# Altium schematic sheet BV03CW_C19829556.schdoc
size 127 x 101 mm
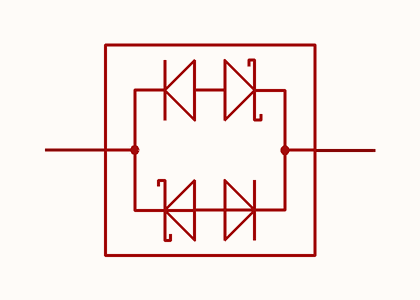
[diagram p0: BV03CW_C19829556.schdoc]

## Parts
U?  bv03cw_c19829556  [SOD-323_L1.7-W1.3-LS2.5-BI-1]  (value not drawn)

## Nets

Not connected (* = marked no-connect by the designer): U? 1 2

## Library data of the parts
U? = bv03cw_c19829556: 反向截止电压(Vrwm):3.3V;钳位电压:16V;峰值脉冲功率(Ppp):250W@8/20us;击穿电压:6V;; Manufacturer: TECH PUBLIC(台舟); ManufacturerPart: BV03CW; AddInBom: yes; ModelId: 5bffd34da2d34048ab2043cf4ece0d8f; ModelTransform: 102.362,51.181,0,0,0,0,0,0,0; Reverse Stand-Off Voltage (Vrwm): 3.3V; Clamping Voltage: 16V; Voltage - Breakdown: 6V; Reverse Leakage Current (Ir): 200nA; Number of Channels: 单路; level of protection: IEC 61000-4-4；IEC 61000-4-2; Junction Capacitance: 1pF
